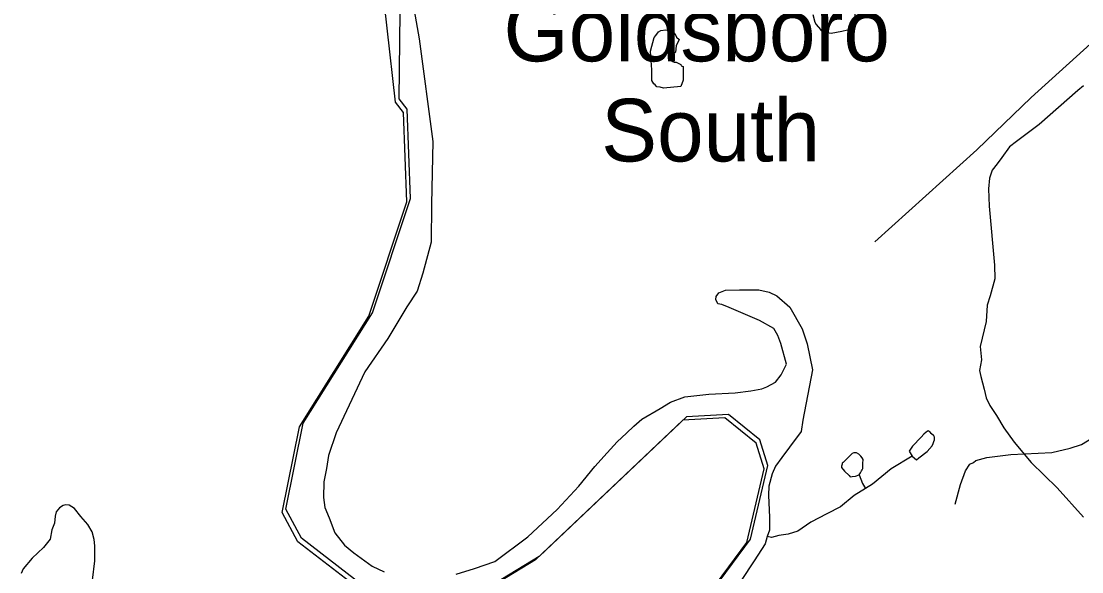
# Model space of a CAD drawing. Extents: x 2260773 to 2342389, y 552869 to 618546.
# Drawn here: x 2290402 to 2293789, y 590931 to 592689 of the extents above; entities that cross this region are included whole.
import ezdxf

# ---------------------------------------------------------------- set-up
doc = ezdxf.new("R2010")
doc.units = 0
for name, color, linetype in [('Exist Boundary Political Urban Extension UEB', 7, 'Continuous'), ('Exist Civil Demographics Community Label', 7, 'Continuous'), ('Exist Hydrographic Creek Single Shore', 7, 'Continuous'), ('Exist Hydrographic Misc Water Feature', 7, 'Continuous'), ('Exist Road Non-System Type 51', 7, 'Continuous')]:
    doc.layers.add(name, color=color, linetype=linetype)

msp = doc.modelspace()

# ---------------------------------------------------------------- linework, layer by layer
at = {"layer": 'Exist Boundary Political Urban Extension UEB'}
for points in [[(2291532.5, 590855.8), (2291297.5, 591037.7), (2291247.5, 591130.5), (2291302.6, 591404.9), (2291524.5, 591757.8), (2291645.5, 592122.7), (2291634.6, 592408.2), (2291609.6, 592441.5), (2291613.2, 592811.7), (2291500.5, 593082.4), (2291196.1, 593353.1), (2290948.1, 593387), (2290677.6, 593319.3)], [(2292401.5, 590589), (2292730.6, 591034.9), (2292786.6, 591269.9), (2292760.5, 591352.4), (2292660.5, 591433.1), (2292526.6, 591426), (2292056.6, 590979.7), (2291890.5, 590878.1)]]:
    msp.add_lwpolyline(points, dxfattribs=at)
at = {"layer": 'Exist Hydrographic Creek Single Shore'}
msp.add_lwpolyline([(2292373.8, 590437.4), (2292389.8, 590578.1), (2292718.9, 591024), (2292774.9, 591259), (2292748.9, 591341.5), (2292648.8, 591422.2), (2292514.9, 591415.1), (2292044.9, 590968.8), (2291878.8, 590867.2), (2291687.9, 590831.7), (2291520.8, 590844.9), (2291285.8, 591026.8), (2291235.8, 591119.6), (2291290.9, 591394), (2291512.8, 591746.9), (2291633.8, 592111.8), (2291622.9, 592397.3), (2291597.9, 592430.6), (2291543.8, 592904)], dxfattribs=at)
at = {"layer": 'Exist Hydrographic Misc Water Feature'}
for points in [[(2291627.2, 592903.8), (2291627.2, 592894.1), (2291673.4, 592632.5), (2291716.6, 592305.2), (2291712.7, 592105.1), (2291711.5, 591983.2), (2291684.6, 591885), (2291667.2, 591827.2), (2291633.8, 591776.7), (2291572.9, 591676), (2291499.9, 591569.4), (2291407.6, 591374.8), (2291384, 591302.5), (2291376.7, 591260.7), (2291369.1, 591218.4), (2291367.2, 591168.4), (2291372.1, 591136.4), (2291386.1, 591102.7), (2291404.3, 591054.9), (2291434.9, 591015.5), (2291464.8, 590991.5), (2291523.1, 590948.3), (2291561.8, 590930.6)], [(2292929.9, 592710.5), (2292936.5, 592686.3), (2292940.4, 592678.5), (2292954.7, 592662.5), (2292962.7, 592654.8), (2292988.6, 592651), (2293022.6, 592657.2), (2293040.9, 592661.3), (2293050.5, 592663.5), (2293056.8, 592665.4), (2293062.4, 592673.5), (2293066.5, 592687.5), (2293064, 592731.7)], [(2292508.7, 592480.3), (2292452.8, 592475.7), (2292442.9, 592478.1), (2292432.5, 592479.6), (2292426.7, 592485.7), (2292422.6, 592489.6), (2292416.3, 592499.5), (2292416.1, 592533.6), (2292411.5, 592593.5), (2292423, 592637.6), (2292429.2, 592643.5), (2292437.2, 592655.7), (2292445, 592659.8), (2292461.2, 592661.8), (2292472.9, 592658), (2292480.9, 592658), (2292489.1, 592650.3), (2292495, 592638.1), (2292503, 592630.4), (2292493.4, 592610.4), (2292491.7, 592590.3), (2292481.5, 592580.1), (2292477.4, 592578.3), (2292469.6, 592574.2), (2292476.1, 592567.9), (2292479.8, 592562.1), (2292487.6, 592558.5), (2292493.6, 592558.4), (2292508.1, 592550.5), (2292510, 592546.6), (2292515.9, 592544.5), (2292516.1, 592532.3), (2292516.3, 592500.7), (2292508.7, 592480.3)], [(2293794, 592482.6), (2293775.8, 592468.3), (2293653.1, 592359.4), (2293579.9, 592304.8), (2293557.6, 592288.3), (2293534, 592254.1), (2293518.4, 592234.1), (2293502.2, 592213.9), (2293494.4, 592187.9), (2293490.9, 592153.9), (2293493.6, 592098), (2293509.6, 591910.3), (2293511.4, 591866.1), (2293496.1, 591812.1), (2293486.4, 591781.9), (2293483.4, 591730.1), (2293464.1, 591649.8), (2293468.2, 591607.9), (2293462.4, 591573.9), (2293466.3, 591554.2), (2293477.2, 591514.1), (2293483.2, 591486.4), (2293495.7, 591462.2), (2293516, 591430.3), (2293540.4, 591390.6), (2293572.8, 591345.1), (2293627.3, 591279.8), (2293709.7, 591198.4), (2293794.6, 591105.3)], [(2291791.7, 590922.8), (2291849.3, 590941.3), (2291914.9, 590963.8), (2292020.3, 591042.8), (2292113.4, 591129.4), (2292182.7, 591204.1), (2292234, 591266.6), (2292273.8, 591310.9), (2292305.3, 591345.4), (2292335.1, 591373.4), (2292358.9, 591395.8), (2292384.5, 591417.9), (2292442.1, 591452.6), (2292476.1, 591472.6), (2292521.9, 591489.2), (2292597.5, 591497.7), (2292681.8, 591502.5), (2292731.6, 591509.1), (2292767.1, 591515.5), (2292783.5, 591521.6), (2292811.4, 591536), (2292829, 591559.8), (2292846.5, 591594), (2292828.2, 591660), (2292818.2, 591685.9), (2292805.5, 591707.7), (2292759.3, 591733.3), (2292663.1, 591774.5), (2292639, 591784.3), (2292626.9, 591786.1), (2292620.7, 591800), (2292621.1, 591810), (2292630.3, 591822), (2292650.8, 591830.3), (2292696.4, 591830.8), (2292758.1, 591831.2), (2292790.9, 591823.4), (2292814.9, 591811.7), (2292856.9, 591776.2), (2292895.5, 591706.7), (2292912.1, 591658.8), (2292928.9, 591575.2), (2292898.3, 591414.7), (2292892.8, 591378.6), (2292855.1, 591328.3), (2292831.5, 591296.2), (2292811.4, 591268), (2292799.7, 591243.8), (2292790.1, 591203.9), (2292788.4, 591175.8), (2292791.3, 591103.9), (2292791.9, 591063.7), (2292783.9, 591043.8)], [(2293247.3, 591300.1), (2293261.5, 591288.2), (2293268.9, 591294.4), (2293295.1, 591314.4), (2293310.9, 591332.7), (2293314.4, 591340.7), (2293316.6, 591346.8), (2293318.5, 591352.6), (2293318.7, 591356.6), (2293318.7, 591360.7), (2293316.6, 591364.7), (2293308.2, 591372.8), (2293304.3, 591376.7), (2293298.4, 591380.4), (2293292.2, 591376.5), (2293284.5, 591370.3), (2293276.5, 591360.2), (2293248.8, 591331.9), (2293237.3, 591316.2), (2293247.3, 591300.1)], [(2293078, 591240.4), (2293082.1, 591246.7), (2293085.6, 591252.7), (2293087.4, 591256.5), (2293089.9, 591260.6), (2293089.7, 591266.7), (2293089.5, 591276.4), (2293091.1, 591288.8), (2293087.4, 591294.5), (2293083.3, 591300.4), (2293077.1, 591306.6), (2293069.2, 591310.3), (2293065, 591310.5), (2293061.2, 591310.3), (2293055.2, 591308.3), (2293049.7, 591302.3), (2293031.2, 591284), (2293027.3, 591280.1), (2293023.4, 591277.8), (2293023.6, 591274.1), (2293021.4, 591268), (2293021.6, 591263.9), (2293031.4, 591252.3), (2293046.2, 591238.3), (2293049.7, 591234.2), (2293055.8, 591234.5), (2293065.9, 591236.6), (2293078, 591240.4)], [(2293247.3, 591300.1), (2293179.9, 591259.6), (2293120.2, 591210.9), (2293097.9, 591196.9)], [(2293078, 591240.4), (2293088.2, 591212.5), (2293097.9, 591196.9)], [(2293097.9, 591196.9), (2293062.4, 591174.2), (2293018.9, 591138.2), (2292975.2, 591115.6), (2292923.2, 591089.3), (2292881.9, 591060.7), (2292851.8, 591050.6), (2292821.7, 591046.2), (2292797.7, 591040.1), (2292783.9, 591043.8)], [(2290630.5, 590903.9), (2290637.8, 590966), (2290637.6, 591013.9), (2290635, 591033.8), (2290628.8, 591057.8), (2290614.9, 591081.4), (2290592.5, 591107.5), (2290572.4, 591133.2), (2290555.8, 591143), (2290544.3, 591144.8), (2290536.3, 591142.7), (2290524.2, 591134.8), (2290514.2, 591122.5), (2290510.5, 591108.5), (2290509.1, 591086.4), (2290500.7, 591064.5), (2290495.3, 591034.5), (2290473.4, 591008.2), (2290437.9, 590973.8), (2290408.2, 590939.8), (2290402.4, 590925.7)], [(2292783.9, 591043.8), (2292778.2, 591019.9), (2292742.9, 590965.7), (2292700.9, 590903), (2292671.6, 590856.8), (2292634, 590810.5), (2292580.7, 590760.2), (2292568.8, 590740), (2292543.2, 590697.7), (2292523.9, 590663.7), (2292499.9, 590617.4), (2292464.7, 590525.4), (2292435.7, 590430.8)]]:
    msp.add_lwpolyline(points, dxfattribs=at)
at = {"layer": 'Exist Road Non-System Type 51'}
for points in [[(2293127.7, 591984.8), (2293453.7, 592278.6), (2293626.9, 592446), (2293861.8, 592657.6), (2293899.1, 592688.3)], [(2293384.2, 591146.9), (2293401.8, 591209.6), (2293417.4, 591252.7), (2293431.1, 591274.2), (2293442.9, 591280.1), (2293450.7, 591286), (2293486, 591295.8), (2293562.3, 591305.6), (2293693.5, 591311.5), (2293752.2, 591325.2), (2293787.4, 591336.9), (2293834.4, 591366.3), (2293863.8, 591393.7), (2293910.8, 591421.1), (2293967.5, 591434.9), (2294081.8, 591446.6)]]:
    msp.add_lwpolyline(points, dxfattribs=at)

# ---------------------------------------------------------------- texts
at = {"layer": 'Exist Civil Demographics Community Label'}
for s, p in [('Goldsboro', (2291942.5, 592561.1)), ('South', (2292254.3, 592241.3))]:
    msp.add_text(s, height=200, dxfattribs=at).set_placement(p)

doc.saveas('drawing.dxf')
